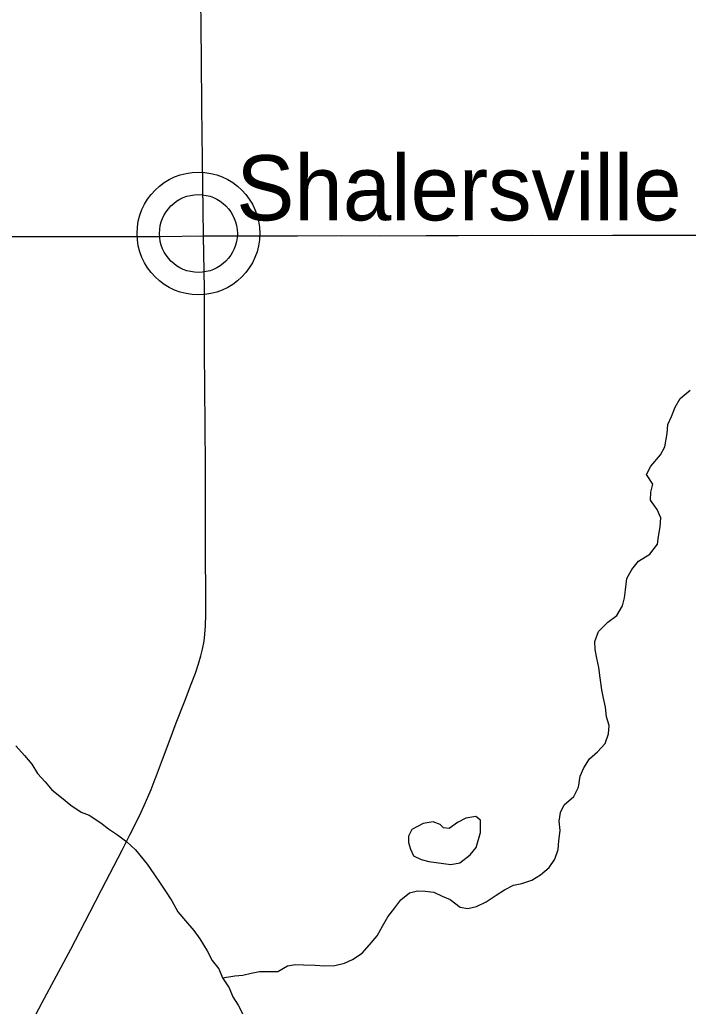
# Model space of a CAD drawing. Extents: x 0 to 34, y 0 to 22.
# Drawn here: x 16.42 to 17.231, y 14.297 to 15.493 of the extents above; entities that cross this region are included whole.
import ezdxf

# ---------------------------------------------------------------- set-up
doc = ezdxf.new("R2010")
doc.units = 0
for name, color, linetype in [('GM_X_Minor_Lake', 7, 'Continuous'), ('GM_X_Minor_River', 7, 'Continuous'), ('GM_X_State_Route', 7, 'Continuous'), ('GM_X_Unincorporated', 7, 'Continuous'), ('GM_X_Unincorporated_Location', 7, 'Continuous'), ('GM_X_Unincorporated_Text', 7, 'Continuous')]:
    doc.layers.add(name, color=color, linetype=linetype)

msp = doc.modelspace()

# ---------------------------------------------------------------- linework, layer by layer
at = {"layer": 'GM_X_Minor_Lake'}
msp.add_line((16.9164, 14.4723), (16.9427, 14.4686), dxfattribs=at)
msp.add_lwpolyline([(16.9427, 14.4686), (16.954, 14.4705), (16.9664, 14.4805), (16.9738, 14.4893), (16.9789, 14.5072), (16.9788, 14.5224), (16.9734, 14.5269), (16.9609, 14.5249), (16.9511, 14.5194), (16.941, 14.5121), (16.9338, 14.5132), (16.93, 14.5169), (16.9216, 14.5202), (16.9095, 14.5182), (16.8956, 14.5112), (16.8915, 14.5028), (16.8916, 14.4952), (16.8939, 14.4872), (16.8978, 14.4793), (16.907, 14.4745), (16.9164, 14.4723)], dxfattribs=at)
at = {"layer": 'GM_X_Minor_River'}
for points in [[(16.6658, 14.3312), (16.6809, 14.3336), (16.6907, 14.3345), (16.7009, 14.3369), (16.7108, 14.3389), (16.7217, 14.3387), (16.7331, 14.3388), (16.7448, 14.3458), (16.7546, 14.3474), (16.7644, 14.3471), (16.7785, 14.3465), (16.7902, 14.3459), (16.8023, 14.346), (16.814, 14.3492), (16.8238, 14.3535), (16.8355, 14.3612), (16.8441, 14.3712), (16.8534, 14.3823), (16.8601, 14.3938), (16.8664, 14.4053), (16.875, 14.416), (16.8821, 14.4256), (16.8926, 14.4344), (16.9025, 14.4368), (16.9119, 14.4362), (16.9222, 14.4352), (16.9324, 14.4303), (16.942, 14.4263), (16.9542, 14.4169), (16.9637, 14.4151), (16.9742, 14.4175), (16.9859, 14.4234), (16.998, 14.4315), (17.0081, 14.4377), (17.019, 14.4435), (17.0289, 14.4455), (17.0413, 14.4495), (17.0518, 14.456), (17.062, 14.4649), (17.069, 14.4752), (17.0731, 14.4867), (17.0737, 14.4973), (17.0755, 14.5099), (17.0742, 14.5212), (17.076, 14.5315), (17.0804, 14.5411), (17.0921, 14.5511), (17.0976, 14.5625), (17.0998, 14.5755), (17.1042, 14.5858), (17.1109, 14.5965), (17.1206, 14.605), (17.13, 14.6153), (17.134, 14.6268), (17.1347, 14.637), (17.1315, 14.6476), (17.1303, 14.6594), (17.1279, 14.67), (17.1262, 14.6802), (17.1238, 14.695), (17.1225, 14.7075), (17.1198, 14.7185), (17.1181, 14.7291), (17.1176, 14.739), (17.122, 14.7512), (17.1333, 14.7623), (17.1442, 14.7704), (17.1509, 14.7823), (17.1534, 14.7918), (17.1548, 14.8017), (17.1562, 14.8154), (17.1625, 14.8261), (17.1703, 14.8361), (17.1843, 14.8446), (17.1936, 14.8568), (17.1946, 14.8663), (17.1968, 14.8778), (17.1974, 14.8888), (17.1931, 14.899), (17.185, 14.9103), (17.1853, 14.9198), (17.1879, 14.9297), (17.1801, 14.9414), (17.1853, 14.9513), (17.1973, 14.9651), (17.2025, 14.975), (17.2053, 14.991), (17.206, 15.002), (17.2104, 15.0116), (17.2148, 15.023), (17.2212, 15.0334), (17.2332, 15.0434)], [(16.4153, 14.6123), (16.4257, 14.6007), (16.4349, 14.5901), (16.4415, 14.5788), (16.451, 14.5687), (16.4591, 14.5589), (16.4709, 14.5499), (16.482, 14.5405), (16.4946, 14.532), (16.5041, 14.5283)], [(16.5041, 14.5283), (16.5183, 14.5189), (16.5278, 14.5118), (16.5385, 14.5047), (16.5499, 14.4961), (16.5603, 14.4864), (16.5745, 14.4691), (16.5829, 14.4574), (16.5903, 14.4461), (16.5968, 14.4363), (16.6045, 14.4246), (16.6119, 14.4114), (16.6211, 14.4005), (16.6311, 14.3885), (16.6387, 14.3783), (16.6476, 14.364), (16.6534, 14.3523), (16.6615, 14.3421), (16.6658, 14.3312), (16.6739, 14.3191), (16.6785, 14.3081), (16.6851, 14.298), (16.6905, 14.287)]]:
    msp.add_lwpolyline(points, dxfattribs=at)
at = {"layer": 'GM_X_State_Route'}
for points in [[(16.6431, 15.2304), (16.6416, 15.3233), (16.641, 15.3861), (16.6404, 15.4451), (16.6395, 15.5563), (16.639, 15.5932), (16.6388, 15.6195)], [(16.2829, 15.2297), (16.3358, 15.2298), (16.3886, 15.2299), (16.4488, 15.2296), (16.591, 15.2297), (16.6431, 15.2304)], [(16.5845, 14.5725), (16.5848, 14.5734), (16.5934, 14.596), (16.6026, 14.6204), (16.61, 14.6402), (16.6198, 14.6657), (16.628, 14.6872), (16.6331, 14.7005), (16.6369, 14.7117), (16.6399, 14.7217), (16.6418, 14.7295), (16.6436, 14.7393), (16.6447, 14.7479), (16.6454, 14.7577), (16.6459, 14.7714), (16.6455, 14.8692), (16.6453, 14.9524), (16.6446, 15.0475), (16.6443, 15.0897), (16.6441, 15.136), (16.644, 15.1663), (16.6431, 15.2304)], [(16.6431, 15.2304), (16.6488, 15.2305), (16.7066, 15.2307), (16.7569, 15.2307), (16.8097, 15.2308), (16.8563, 15.2307), (16.9128, 15.2308), (16.952, 15.2309), (17.0421, 15.2312), (17.0863, 15.231), (17.1391, 15.2312), (17.2043, 15.2314), (17.2577, 15.2313), (17.295, 15.2314), (17.3367, 15.2314), (17.3945, 15.2319), (17.4721, 15.232), (17.4951, 15.2321), (17.5342, 15.2321), (17.6719, 15.232), (17.6898, 15.232), (17.6992, 15.232)], [(16.5194, 14.438), (16.5446, 14.4867), (16.5536, 14.5045), (16.5571, 14.5113), (16.5672, 14.5322), (16.5725, 14.5436), (16.5793, 14.5596), (16.5845, 14.5725)], [(16.4392, 14.2859), (16.4475, 14.3013), (16.4648, 14.3335), (16.4819, 14.3659), (16.5052, 14.4106), (16.5194, 14.438)]]:
    msp.add_lwpolyline(points, dxfattribs=at)
at = {"layer": 'GM_X_Unincorporated'}
for radius in [0.0744, 0.0472]:
    msp.add_circle((16.6368, 15.2334), radius, dxfattribs=at)
at = {"layer": 'GM_X_Unincorporated_Location'}
msp.add_line((16.6368, 15.2334), (16.6368, 15.2334), dxfattribs=at)

# ---------------------------------------------------------------- texts
at = {"layer": 'GM_X_Unincorporated_Text'}
msp.add_text('Shalersville', height=0.078977, rotation=0, dxfattribs=at).set_placement((16.6827, 15.2493))

doc.saveas('drawing.dxf')
